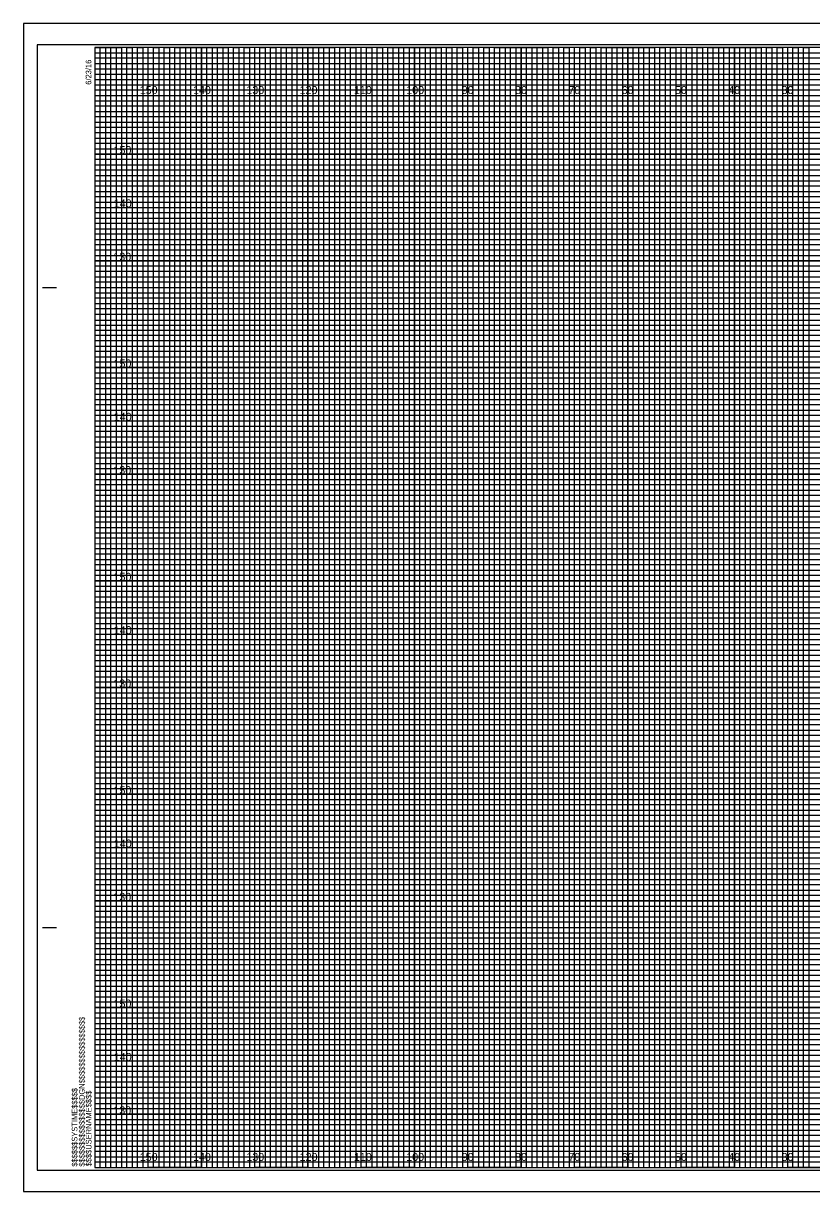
# Model space of a CAD drawing. Extents: x -13 to 323, y -5 to 434.
# Drawn here: x -13.4 to 134.5, y -4.5 to 214.5 of the extents above; entities that cross this region are included whole.
import ezdxf

# ---------------------------------------------------------------- set-up
doc = ezdxf.new("R2010")
doc.units = 0
for name, color, linetype in [('Exist Cross Section Cell', 7, 'Continuous'), ('Exist XS Center Line Elevation Label', 7, 'Continuous'), ('Exist XS Ground Line', 7, 'Continuous'), ('Prop CMT Pvmt Course 2', 7, 'Continuous'), ('Prop CMT Pvmt Course 3', 7, 'Continuous'), ('Prop CMT Pvmt Surface', 7, 'Continuous'), ('Prop CMT Pvmt Surface Shoulder', 7, 'Continuous'), ('Prop CMT Shld Paved Course 1', 7, 'Continuous'), ('Prop CMT Shld Paved Course 2', 7, 'Continuous'), ('Prop CMT Shld Paved Course 3', 7, 'Continuous'), ('Prop CMT Subgrade Earthwork', 7, 'Continuous')]:
    doc.layers.add(name, color=color, linetype=linetype)

msp = doc.modelspace()

# ---------------------------------------------------------------- linework, layer by layer
at = {"layer": 'Exist XS Center Line Elevation Label'}
for points in [[(0, 210), (5, 210), (5, 0), (15, 0), (15, 210), (25, 210), (25, 0), (35, 0), (35, 210), (45, 210), (45, 0), (55, 0), (55, 210), (65, 210), (65, 0), (75, 0), (75, 210), (85, 210), (85, 0), (95, 0), (95, 210), (105, 210), (105, 0), (115, 0), (115, 210), (125, 210), (125, 0), (135, 0)], [(0, 205), (275, 205)], [(0, 185), (320, 185), (320, 195), (0, 195)], [(0, 165), (320, 165), (320, 175), (0, 175)], [(0, 145), (320, 145), (320, 155), (0, 155)], [(0, 125), (320, 125), (320, 135), (0, 135)], [(0, 105), (320, 105), (320, 115), (0, 115)], [(0, 85), (320, 85), (320, 95), (0, 95)], [(0, 65), (320, 65), (320, 75), (0, 75)], [(0, 45), (320, 45), (320, 55), (0, 55)], [(0, 25), (320, 25), (320, 35), (0, 35)], [(0, 5), (320, 5), (320, 15), (0, 15)]]:
    msp.add_lwpolyline(points, dxfattribs=at)
at = {"layer": 'Exist XS Ground Line'}
for p, q in [((10, 210), (0, 210)), ((10, 0), (10, 210)), ((30, 210), (20, 210)), ((20, 210), (20, 0)), ((30, 0), (30, 210)), ((50, 210), (40, 210)), ((40, 210), (40, 0)), ((50, 0), (50, 210)), ((70, 210), (60, 210)), ((60, 210), (60, 0)), ((70, 0), (70, 210)), ((90, 210), (80, 210)), ((80, 210), (80, 0)), ((90, 0), (90, 210)), ((110, 210), (100, 210)), ((100, 210), (100, 0)), ((110, 0), (110, 210)), ((130, 210), (120, 210)), ((120, 210), (120, 0)), ((130, 0), (130, 210)), ((20, 0), (10, 0)), ((40, 0), (30, 0)), ((60, 0), (50, 0)), ((80, 0), (70, 0)), ((100, 0), (90, 0)), ((120, 0), (110, 0)), ((140, 0), (130, 0))]:
    msp.add_line(p, q, dxfattribs=at)
for points in [[(0, 200), (320, 200), (320, 190), (0, 190)], [(0, 180), (320, 180), (320, 170), (0, 170)], [(0, 160), (320, 160), (320, 150), (0, 150)], [(0, 140), (320, 140), (320, 130), (0, 130)], [(0, 120), (320, 120), (320, 110), (0, 110)], [(0, 100), (320, 100), (320, 90), (0, 90)], [(0, 80), (320, 80), (320, 70), (0, 70)], [(0, 60), (320, 60), (320, 50), (0, 50)], [(0, 40), (320, 40), (320, 30), (0, 30)], [(0, 20), (320, 20), (320, 10), (0, 10)]]:
    msp.add_lwpolyline(points, dxfattribs=at)
at = {"layer": 'Prop CMT Pvmt Course 2'}
for p, q in [((0, 209), (260, 209)), ((260, 207.98), (0, 207.98)), ((0, 207.98), (0, 207)), ((0, 207), (260, 207)), ((260, 205.89), (0, 205.89)), ((0, 205.89), (0, 204)), ((0, 204), (320, 204))]:
    msp.add_line(p, q, dxfattribs=at)
for points in [[(0, 203), (270, 203), (320, 203), (320, 202), (0, 202)], [(0, 201), (320, 201), (320, 199), (0, 199)], [(0, 198), (320, 198), (320, 197), (0, 196.98)], [(0, 196), (320, 196), (320, 194), (0, 194)], [(0, 193), (320, 193), (320, 192), (0, 192)], [(0, 191), (320, 191), (320, 189), (0, 189)], [(0, 188), (320, 188), (320, 187), (0, 187)], [(0, 186), (320, 186), (320, 184), (0, 184)], [(0, 183), (320, 183), (320, 182), (0, 182)], [(0, 181), (320, 181), (320, 179), (0, 179)], [(0, 178), (320, 178), (320, 177), (0, 177)], [(0, 176), (320, 176), (320, 173.95), (320, 173), (320, 172), (0, 172)], [(0, 174), (320, 174), (320, 173), (0, 173)], [(0, 171), (320, 171), (320, 169), (0, 169.03)], [(0, 169.03), (320, 169), (320, 168), (0, 168)], [(0, 167), (320, 167), (320, 166), (0, 166)], [(0, 164), (320, 164), (320, 163), (0, 163)], [(0, 162), (320, 162), (320, 161), (0, 161)], [(-0.07, 158.89), (320, 158.89), (320, 157.88), (-0.07, 157.88)], [(0, 157), (320, 157), (320, 156), (0, 156)], [(0, 154), (320, 154), (320, 153), (0, 153)], [(0, 152), (320, 152), (320, 151), (0, 151)], [(0, 149), (320, 149), (320, 148), (0, 148)], [(0, 147), (320, 147), (320, 146), (0, 146)], [(0, 144), (320, 144), (320, 143), (0, 143)], [(0, 142), (320, 142), (320, 141), (0, 141)], [(0, 139), (320, 139), (319.99, 137.98), (0, 138)], [(0, 137), (320, 137), (320, 136), (0, 136)], [(0, 134), (320, 134), (320, 133), (0, 133)], [(0, 132), (320, 132), (320, 131), (0, 131)], [(0, 129), (320, 129), (320, 128), (0, 128)], [(0, 127), (320, 127), (320, 126), (0, 126)], [(0, 124), (320, 124), (320, 123), (0, 123)], [(0, 122), (320, 122), (320, 121), (0, 121)], [(0, 119), (320, 119), (320, 118), (0, 118)], [(0, 116.99), (320.07, 116.91), (320, 116), (0, 116)], [(0, 114), (320, 114), (320, 113), (0, 113)], [(0, 112), (320, 112), (320, 111), (0, 111)], [(0, 109), (320, 109), (320, 108), (0, 108)], [(0, 107), (320, 107), (320, 106), (0, 106)], [(0, 104), (320, 104), (320, 103), (0, 103)], [(0, 102), (320, 102), (320, 101), (0, 101)], [(0, 99), (320, 99), (320, 98), (0, 98)], [(0, 97), (320, 97), (320, 96), (0, 96)], [(0, 94), (320, 94), (320, 93), (0, 93)], [(0, 92), (320, 92), (320, 91), (0, 91)], [(0, 89), (320, 89), (320, 88), (0, 88)], [(0, 87), (320, 87), (320, 86), (0, 86)], [(0, 84), (320, 84), (320, 83), (0, 83)], [(0, 82), (320, 82), (320, 81), (0, 81)], [(0, 79), (320, 79), (319.99, 77.98), (0, 78)], [(0, 77), (320, 77), (320, 76), (0, 76)], [(0, 74), (320, 74), (320, 73), (0, 73)], [(0, 72), (320, 72), (320, 71), (0, 71)], [(0, 69), (320, 69), (320, 68), (0, 68)], [(0, 67), (320, 67), (320, 66), (0, 66)], [(0, 64), (320, 64), (320, 63), (0, 63)], [(0, 62), (320, 62), (320, 61), (0, 61)], [(0, 59), (320, 59), (320, 58), (0, 58)], [(0, 56.99), (320.07, 56.91), (320, 56), (0, 56)], [(0, 54), (320, 54), (320, 53), (0, 53)], [(0, 52), (320, 52), (320, 51), (0, 51)], [(0, 49), (320, 49), (320, 48), (0, 48)], [(0, 47), (320, 47), (320, 46), (0, 46)], [(0, 44), (320, 44), (320, 43), (0, 43)], [(0, 42), (320, 42), (320, 41), (0, 41)], [(0, 39), (320, 39), (320, 38), (0, 38)], [(0, 37), (320, 37), (320, 36), (0, 36)], [(0, 34), (320, 34), (320, 33), (0, 33)], [(0, 32), (320, 32), (320, 31), (0, 31)], [(0, 29), (320, 29), (320, 28), (0, 28)], [(0, 27), (320, 27), (320, 26), (0, 26)], [(0, 24), (320, 24), (320, 23), (0, 23)], [(0, 22), (320, 22), (320, 21), (0, 21)], [(0, 19), (320, 19), (320, 18), (0, 18)], [(0, 17), (320, 17), (320, 16), (0, 16)], [(0, 14), (320, 14), (320, 13), (0, 13)], [(0, 12), (320, 12), (320, 11), (0, 11)], [(0, 9), (320, 9), (320, 8), (0, 8)], [(0, 7), (320, 7), (320, 6), (0, 6)], [(0, 4), (320, 4), (320, 3), (0, 3)], [(0, 2), (320, 2), (320, 1), (0, 1)]]:
    msp.add_lwpolyline(points, dxfattribs=at)
at = {"layer": 'Prop CMT Pvmt Course 3'}
for p, q in [((-9.8, 165), (-7.3, 165)), ((-9.7, 165), (-7.2, 165)), ((-9.8, 45), (-7.3, 45)), ((-9.7, 45), (-7.2, 45)), ((0, 0), (0, 0)), ((0, 0), (0, 0)), ((0, 0), (0, 0)), ((0, 0), (0, 0)), ((0, 0), (0, 0)), ((0, 0), (0, 0)), ((0, 0), (0, 0))]:
    msp.add_line(p, q, dxfattribs=at)
msp.add_lwpolyline([(320, 210), (0, 210), (0, 0), (320, 0)], close=True, dxfattribs=at)
at = {"layer": 'Prop CMT Pvmt Surface'}
for points in [[(0, 0), (1, 0), (1, 210), (2, 210), (2, 0)], [(2, 0), (3, 0), (3, 210), (4, 210), (4, 0)], [(5, 0), (6, 0), (6, 210), (7, 210), (7, 0)], [(7, 0), (8, 0), (8, 210), (9, 210), (9, 0)], [(10, 0), (11, 0), (11, 210), (12, 210), (12, 0)], [(12, 0), (13, 0), (13, 210), (14, 210), (14, 0)], [(15, 0), (16, 0), (16, 210), (17, 210), (17, 0)], [(17, 0), (18, 0), (18, 210), (19, 210), (19, 0)], [(20, 0), (21, 0), (21, 210), (22, 210), (22, 0)], [(22, 0), (23, 0), (23, 210), (24, 210), (24, 0)], [(25, 0), (26, 0), (26, 210), (27, 210), (27, 0)], [(27, 0), (28, 0), (28, 210), (29, 210), (29, 0)], [(30, 0), (31, 0), (31, 210), (32, 210), (32, 0)], [(32, 0), (33, 0), (33, 210), (34, 210), (34, 0)], [(35, 0), (36, 0), (36, 210), (37, 210), (37, 0)], [(37, 0), (38, 0), (38, 210), (39, 210), (39, 0)], [(40, 0), (41, 0), (41, 210), (42, 210), (42, 0)], [(42, 0), (43, 0), (43, 210), (44, 210), (44, 0)], [(45, 0), (46, 0), (46, 210), (47, 210), (47, 0)], [(47, 0), (48, 0), (48, 210), (49, 210), (49, 0)], [(50, 0), (51, 0), (51, 210), (52, 210), (52, 0)], [(52, 0), (53, 0), (53, 210), (54, 210), (54, 0)], [(55, 0), (56, 0), (56, 210), (57, 210), (57, 0)], [(57, 0), (58, 0), (58, 210), (59, 210), (59, 0)], [(60, 0), (61, 0), (61, 210), (62, 210), (62, 0)], [(62, 0), (63, 0), (63, 210), (64, 210), (64, 0)], [(65, 0), (66, 0), (66, 210), (67, 210), (67, 0)], [(67, 0), (68, 0), (68, 210), (69, 210), (69, 0)], [(70, 0), (71, 0), (71, 210), (72, 210), (72, 0)], [(72, 0), (73, 0), (73, 210), (74, 210), (74, 0)], [(75, 0), (76, 0), (76, 210), (77, 210), (77, 0)], [(77, 0), (78, 0), (78, 210), (79, 210), (79, 0)], [(80, 0), (81, 0), (81, 210), (82, 210), (82, 0)], [(82, 0), (83, 0), (83, 210), (84, 210), (84, 0)], [(85, 0), (86, 0), (86, 210), (87, 210), (87, 0)], [(87, 0), (88, 0), (88, 210), (89, 210), (89, 0)], [(90, 0), (91, 0), (91, 210), (92, 210), (92, 0)], [(92, 0), (93, 0), (93, 210), (94, 210), (94, 0)], [(95, 0), (96, 0), (96, 210), (97, 210), (97, 0)], [(97, 0), (98, 0), (98, 210), (99, 210), (99, 0)], [(100, 0), (101, 0), (101, 210), (102, 210), (102, 0)], [(102, 0), (103, 0), (103, 210), (104, 210), (104, 0)], [(105, 0), (106, 0), (106, 210), (107, 210), (107, 0)], [(107, 0), (108, 0), (108, 210), (109, 210), (109, 0)], [(110, 0), (111, 0), (111, 210), (112, 210), (112, 0)], [(112, 0), (113, 0), (113, 210), (114, 210), (114, 0)], [(115, 0), (116, 0), (116, 210), (117, 210), (117, 0)], [(117, 0), (118, 0), (118, 210), (119, 210), (119, 0)], [(120, 0), (121, 0), (121, 210), (122, 210), (122, 0)], [(122, 0), (123, 0), (123, 210), (124, 210), (124, 0)], [(125, 0), (126, 0), (126, 210), (127, 210), (127, 0)], [(127, 0), (128, 0), (128, 210), (129, 210), (129, 0)], [(130, 0), (131, 0), (131, 210), (132, 210), (132, 0)], [(132, 0), (133, 0), (133, 210), (134, 210), (134, 0)]]:
    msp.add_lwpolyline(points, dxfattribs=at)
at = {"layer": 'Prop CMT Pvmt Surface Shoulder'}
msp.add_lwpolyline([(-10.8, -0.5), (322.4, -0.5), (322.4, 210.5), (-10.8, 210.5)], close=True, dxfattribs=at)
at = {"layer": 'Prop CMT Shld Paved Course 1'}
for p, q in [((10, 0), (10, 210)), ((20, 0), (20, 210)), ((30, 0), (30, 210)), ((40, 0), (40, 210)), ((50, 0), (50, 210)), ((60, 0), (60, 210)), ((70, 0), (70, 210)), ((80, 0), (80, 210)), ((90, 0), (90, 210)), ((100, 0), (100, 210)), ((110, 0), (110, 210)), ((120, 0), (120, 210)), ((130, 0), (130, 210)), ((0, 200), (320, 200)), ((0, 190), (320, 190)), ((0, 180), (320, 180)), ((0, 170), (320, 170)), ((0, 160), (320, 160)), ((0, 150), (320, 150)), ((0, 140), (320, 140)), ((0, 130), (320, 130)), ((0, 120), (320, 120)), ((0, 110), (320, 110)), ((0, 100), (320, 100)), ((0, 90), (320, 90)), ((0, 80), (320, 80)), ((0, 70), (320, 70)), ((0, 60), (320, 60)), ((0, 50), (320, 50)), ((0, 40), (320, 40)), ((0, 30), (320, 30)), ((0, 20), (320, 20)), ((0, 10), (320, 10))]:
    msp.add_line(p, q, dxfattribs=at)
at = {"layer": 'Prop CMT Shld Paved Course 2'}
for p, q in [((323.3, 214.5), (-13.4, 214.5)), ((-13.4, 214.5), (-13.4, -4.5)), ((-13.4, -4.5), (323.3, -4.5))]:
    msp.add_line(p, q, dxfattribs=at)
at = {"layer": 'Prop CMT Subgrade Earthwork'}
msp.add_lwpolyline([(-13.4, -4.5), (323.3, -4.5), (323.3, 214.5), (-13.4, 214.5)], close=True, dxfattribs=at)

# ---------------------------------------------------------------- texts
at = {"layer": 'Exist Cross Section Cell'}
for s, p in [('150', (8.44, 201.25)), ('140', (18.44, 201.25)), ('130', (28.44, 201.25)), ('120', (38.44, 201.25)), ('110', (48.62, 201.25)), ('100', (58.44, 201.25)), ('90', (68.86, 201.25)), ('80', (78.86, 201.25)), ('70', (88.86, 201.25)), ('60', (98.86, 201.25)), ('50', (108.86, 201.25)), ('40', (118.86, 201.25)), ('30', (128.86, 201.25)), ('150', (8.44, 1.25)), ('140', (18.44, 1.25)), ('130', (28.44, 1.25)), ('120', (38.44, 1.25)), ('110', (48.62, 1.25)), ('100', (58.44, 1.25)), ('90', (68.86, 1.25)), ('80', (78.86, 1.25)), ('70', (88.86, 1.25)), ('60', (98.86, 1.25)), ('50', (108.86, 1.25)), ('40', (118.86, 1.25)), ('30', (128.86, 1.25))]:
    msp.add_text(s, height=1.5, dxfattribs=at).set_placement(p)
at = {"layer": 'Prop CMT Pvmt Course 3'}
for s, p in [('6/23/16', (-0.65, 203)), ('$$$$$$$$$$$$$$$$DGN$$$$$$$$$$$$$$$$', (-1.88, 0.18)), ('$$$$$$SYSTIME$$$$$', (-3.26, 0.18)), ('$$$$USERNAME$$$$', (-0.62, 0.23))]:
    msp.add_text(s, height=1.05, rotation=90, dxfattribs=at).set_placement(p)
at = {"layer": 'Prop CMT Shld Paved Course 3'}
for s, p in [('150', (3.52, 190)), ('140', (3.57, 180)), ('130', (3.49, 170)), ('150', (3.52, 150)), ('140', (3.57, 140)), ('130', (3.49, 130)), ('150', (3.52, 110)), ('140', (3.57, 100)), ('130', (3.49, 90)), ('150', (3.52, 70)), ('140', (3.57, 60)), ('130', (3.49, 50)), ('150', (3.52, 30)), ('140', (3.57, 20)), ('130', (3.49, 10))]:
    msp.add_text(s, height=1.5, dxfattribs=at).set_placement(p)

doc.saveas('drawing.dxf')
